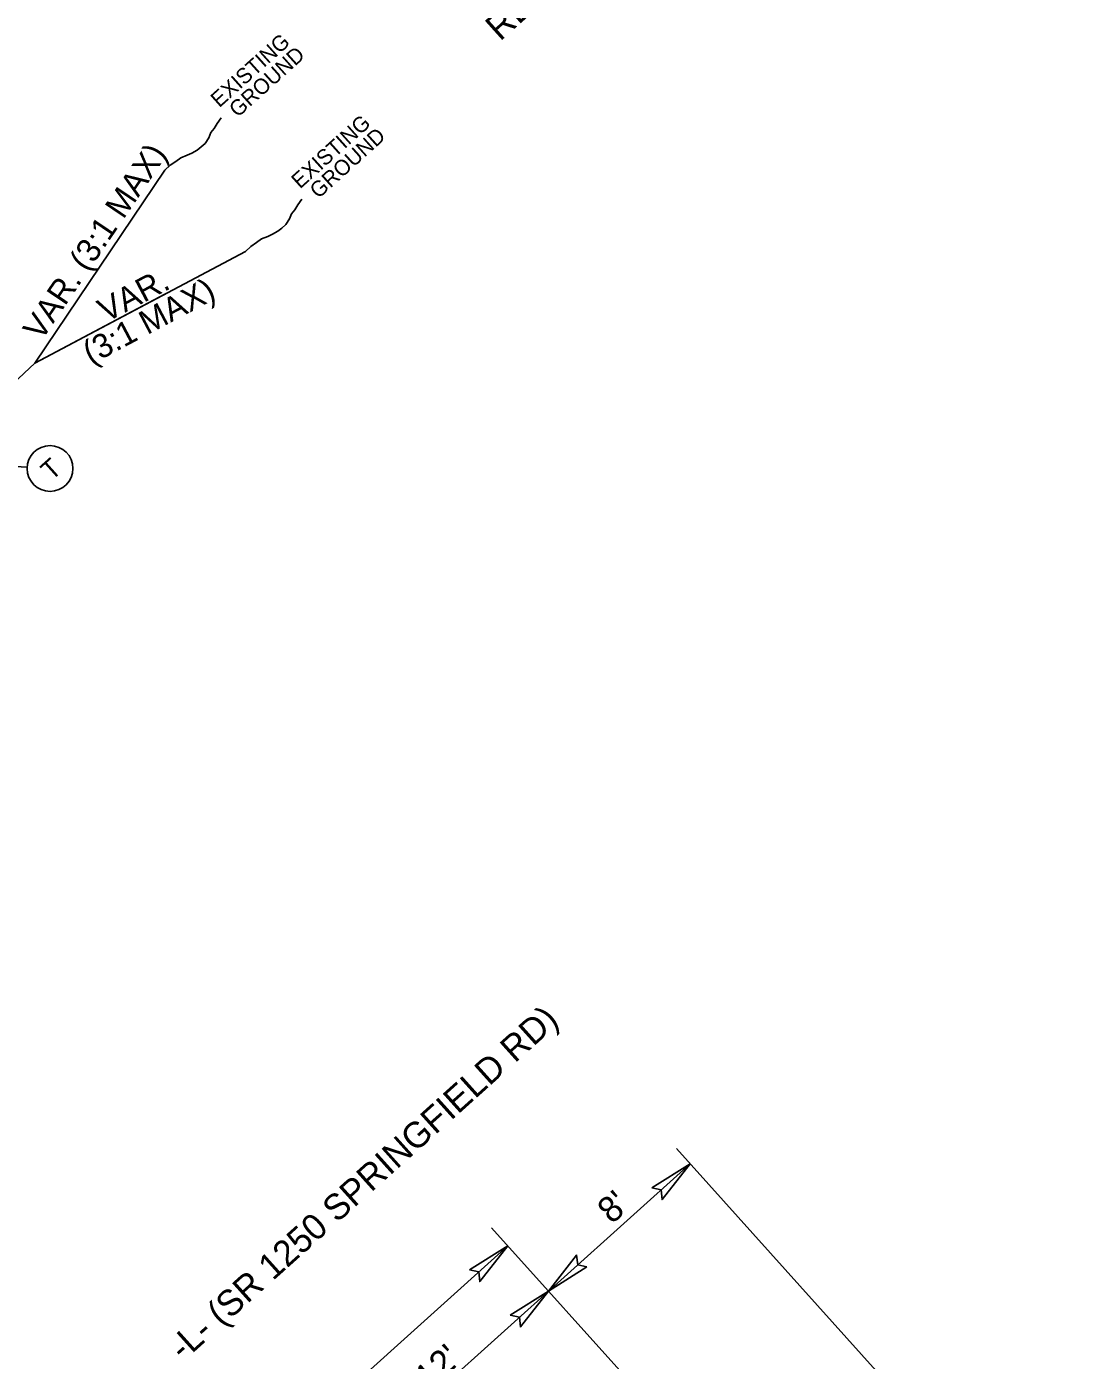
# Model space of a CAD drawing. Extents: x 2488411 to 2488707, y 383669 to 383962.
# Drawn here: x 2488602.1 to 2488646.1, y 383844.8 to 383900.8 of the extents above; entities that cross this region are included whole.
import ezdxf

# ---------------------------------------------------------------- set-up
doc = ezdxf.new("R2010")
doc.units = 0
for name, color, linetype in [('Old_Level_44', 7, 'Continuous'), ('Prop DSN Text', 7, 'Continuous'), ('Prop Roadway Profile Bench Mark Info Text', 7, 'Continuous'), ('Prop Vertical Profile Curve Label', 7, 'Continuous'), ('Sheet Sticker Preliminary CELL', 7, 'Continuous'), ('Sheet Title CELL', 7, 'Continuous'), ('Typical Text General CELL', 7, 'Continuous'), ('Typical Text ID Circle CELL', 7, 'Continuous')]:
    doc.layers.add(name, color=color, linetype=linetype)

msp = doc.modelspace()

# ---------------------------------------------------------------- linework, layer by layer
at = {"layer": 'Prop DSN Text'}
msp.add_line((2488602.106, 383882.32), (2488598.304, 383882.521), dxfattribs=at)
msp.add_circle((2488603.067, 383882.268), 0.962, dxfattribs=at)
at = {"layer": 'Prop Vertical Profile Curve Label'}
msp.add_line((2488596.956, 383881.563), (2488602.427, 383886.692), dxfattribs=at)
at = {"layer": 'Sheet Sticker Preliminary CELL'}
for points in [[(2488628.346, 383852.064), (2488629.956, 383853.077), (2488628.777, 383851.569), (2488628.733, 383851.977)], [(2488620.688, 383848.621), (2488622.298, 383849.634), (2488621.119, 383848.126), (2488621.074, 383848.534)], [(2488625.619, 383848.744), (2488624.009, 383847.73), (2488625.188, 383849.238), (2488625.233, 383848.83)], [(2488622.399, 383846.717), (2488624.009, 383847.73), (2488622.83, 383846.222), (2488622.785, 383846.63)]]:
    msp.add_lwpolyline(points, close=True, dxfattribs=at)
at = {"layer": 'Sheet Title CELL'}
for p, q in [((2488640.989, 383840.807), (2488629.385, 383853.715)), ((2488591.299, 383818.326), (2488629.958, 383853.078)), ((2488634.692, 383835.847), (2488621.618, 383850.39)), ((2488595.537, 383825.577), (2488622.298, 383849.634))]:
    msp.add_line(p, q, dxfattribs=at)
at = {"layer": 'Typical Text General CELL'}
for q in [(2488607.894, 383894.793), (2488611.282, 383891.384), (2488607.891, 383889.587)]:
    msp.add_line((2488602.427, 383886.692), q, dxfattribs=at)
at = {"layer": 'Typical Text ID Circle CELL'}
for points in [[(2488607.894, 383894.793), (2488608.119, 383895.002), (2488608.35, 383895.163), (2488608.568, 383895.312), (2488608.822, 383895.422), (2488609.024, 383895.51), (2488609.241, 383895.635), (2488609.422, 383895.774), (2488609.578, 383895.914), (2488609.739, 383896.153), (2488609.825, 383896.371), (2488609.957, 383896.537), (2488610.093, 383896.753), (2488610.254, 383896.992)], [(2488611.282, 383891.384), (2488611.507, 383891.593), (2488611.739, 383891.754), (2488611.957, 383891.903), (2488612.21, 383892.013), (2488612.413, 383892.101), (2488612.63, 383892.226), (2488612.811, 383892.364), (2488612.967, 383892.505), (2488613.128, 383892.744), (2488613.214, 383892.962), (2488613.346, 383893.128), (2488613.481, 383893.343), (2488613.642, 383893.582)]]:
    msp.add_lwpolyline(points, dxfattribs=at)

# ---------------------------------------------------------------- texts
at = {"layer": 'Old_Level_44'}
msp.add_text('T', height=0.8, rotation=41.9538, dxfattribs=at).set_placement((2488603.129, 383881.729))
at = {"layer": 'Prop Roadway Profile Bench Mark Info Text'}
for s, rotation, p in [('VAR. (3:1 MAX)', 55.9901, (2488602.696, 383887.584)), ('(3:1 MAX)', 27.9176, (2488604.786, 383886.612)), ('VAR.', 27.9176, (2488605.424, 383888.385))]:
    msp.add_text(s, height=1, rotation=rotation, dxfattribs=at).set_placement(p)
at = {"layer": 'Sheet Title CELL'}
for s, height, p in [('REPLACE WITH SELECT MAT. CL. II, TYPE 2 (L)', 1.0817, (2488621.973, 383900.181)), ('EXISTING', 0.65, (2488610.178, 383897.393)), ('GROUND', 0.65, (2488610.95, 383896.978)), ('EXISTING', 0.65, (2488613.567, 383893.983)), ('GROUND', 0.65, (2488614.339, 383893.569)), ('-L- (SR 1250 SPRINGFIELD RD)', 1.0817, (2488608.663, 383844.76)), ("8'", 1.0817, (2488626.671, 383850.51)), ("12'", 1.0817, (2488618.995, 383843.517))]:
    msp.add_text(s, height=height, rotation=41.9538, dxfattribs=at).set_placement(p)

doc.saveas('drawing.dxf')
